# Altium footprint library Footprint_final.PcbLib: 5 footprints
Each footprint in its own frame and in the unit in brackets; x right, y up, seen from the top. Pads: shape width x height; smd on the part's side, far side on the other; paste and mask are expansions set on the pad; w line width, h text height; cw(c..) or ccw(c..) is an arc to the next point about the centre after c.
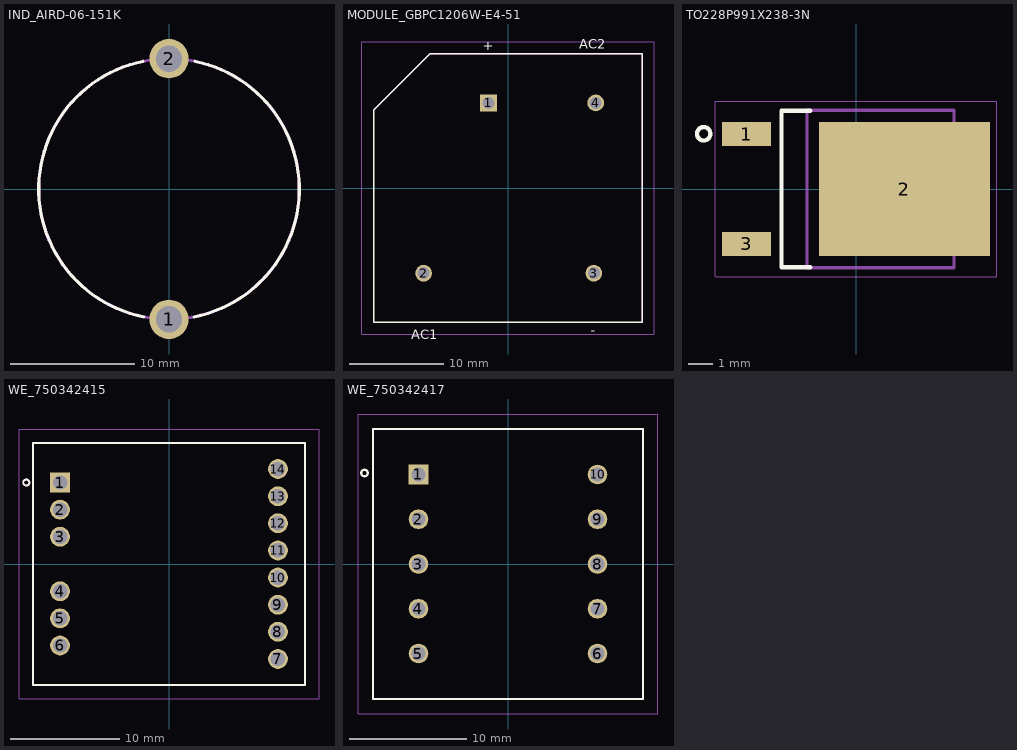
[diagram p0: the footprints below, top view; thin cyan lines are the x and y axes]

## IND_AIRD-06-151K [mm]
height 21
pads (2):
  round 3.175 hole 2.108: 1(0,-10.5) 2(0,10.5)
Top Overlay:
  lines w0.254: -2.086,10.291 ccw(c0,0) -2.035,-10.301 ; 2.035,-10.301 ccw(c0,0) 2.086,10.291
Mechanical 1:
  circle w0.254: c0,0 r10.5
Mechanical 5:
  text ".Designator" at -3.81,-0.381 h1.02
3D body: height 21.5, standoff 0.5, extent -10.417,-10.479 10.5,10.479

## MODULE_GBPC1206W-E4-51 [mm] "RECTIFIER 12A 600V GBPCW-4TH"
height 7.87
pads (4):
  rect 1.774x1.774 / inner round 1.774 / far side rect 1.774x1.774 hole 1.274: 1(-2.075,9.05)
  round 1.774 hole 1.274: 2(-8.975,-9.05) 3(9.125,-9.05) 4(9.325,9.05)
Top Overlay:
  lines w0.178: -14.275,-14.275 14.275,-14.275 14.275,14.275 -8.3,14.275 -14.275,8.3 -14.275,-14.275
  text ".Designator" at -1.524,16.5 h1.02
  text "AC2" at 7.57,14.828 h1.02
  text "AC1" at -10.273,-16.047 h1.02
  text "+" at -2.699,14.665 h1.02
  text "-" at 8.777,-15.583 h1.02
Bottom Overlay:
  lines w0.178: -14.275,-14.275 -14.275,-10 ; -14.275,-8.275 -14.275,-4 ; -14.275,-2.275 -14.275,2 ; -14.275,3.725 -14.275,8 ; -14,-14.275 -9.725,-14.275 ; -13.335,9.24 -9.271,13.304 ; -8,-14.275 -3.725,-14.275 ; -8,14.275 -4,14.275 ; -2.275,14.275 2,14.275 ; -2,-14.275 2.275,-14.275 ; 3.725,14.275 8,14.275 ; 4,-14.275 8.275,-14.275 ; 9.725,14.275 14,14.275 ; 10,-14.275 14.275,-14.275 ; 14.275,-14 14.275,-9.725 ; 14.275,-8 14.275,-3.725 ; 14.275,-2 14.275,2.275 ; 14.275,4 14.275,8.275 ; 14.275,10 14.275,14.275
Mechanical 5:
  lines w0.127: -14.275,-14.275 -14.275,8.3 -8.3,14.275 14.275,14.275 14.275,-14.275 -14.275,-14.275
  text ".Designator" at -1.524,-0.508 h1.02
  text "+" at -2.699,14.665 h1.02
  text "-" at 8.777,-15.583 h1.02
Mechanical 15:
  lines w0.05: -15.545,-15.545 15.545,-15.545 15.545,15.545 -15.545,15.545 -15.545,-15.545
Mechanical 17:
  text "LEAD LENGTH : 23.93MM" at -13.2,4.2 h1.27
3D body: height 7.87, standoff 0, extent -14.275,-14.275 14.275,14.275

## TO228P991X238-3N [mm] "IC, MOSFET N-CH, 500V, 200MA, DPAK"
height 2.38
pads (3):
  rect 2.05x1 smd: 1(-4.55,2.28) 3(-4.55,-2.28)
  rect 7.1x5.55 smd: 2(2,0)
Top Overlay:
  circle w0.178: c-6.326,2.291 r0.279
  lines w0.178: -1.9,-3.25 -3.1,-3.25 -3.1,3.25 -1.9,3.25
  text ".Designator" at -1.524,4 h1.02
Top Paste:
  region: 3.36,0.38 4.96,0.38 4.96,2.02 3.36,2.02
  region: 1.2,0.38 2.8,0.38 2.8,2.02 1.2,2.02
  region: -0.96,0.38 0.64,0.38 0.64,2.02 -0.96,2.02
  region: 3.36,-2.02 4.96,-2.02 4.96,-0.38 3.36,-0.38
  region: 1.2,-2.02 2.8,-2.02 2.8,-0.38 1.2,-0.38
  region: -0.96,-2.02 0.64,-2.02 0.64,-0.38 -0.96,-0.38
Mechanical 5:
  circle w0.127: c-6.326,2.291 r0.279
  lines w0.127: 4.065,-2.668 4.359,-2.668 4.955,-2.006 4.955,2.006 4.359,2.668 4.065,2.668 ; -2.03,-3.27 4.065,-3.27 4.065,3.27 -2.03,3.27 -2.03,-3.27
  text ".Designator" at -1.524,-0.508 h1.02
Mechanical 15:
  lines w0.05: -5.85,-3.65 -5.85,3.65 5.85,3.65 5.85,-3.65 -5.85,-3.65
Mechanical 20:
  circle w0.05: c0,0 r0.35
  lines w0.05: -0.5,0 0.5,0 ; 0,-0.5 0,0.5
3D body: height 2.38, standoff 0, extent -2.03,-3.27 4.065,3.27

## WE_750342415 [mm] "TRANSFOERMER, TH, 14-PIN"
height 16
pads (14):
  rect 1.82x1.82 / inner round 1.82 / far side rect 1.82x1.82 hole 1.32: 1(-10,7.48)
  round 1.82 hole 1.32: 2(-10,4.99) 3(-10,2.5) 4(-10,-2.5) 5(-10,-4.99) 6(-10,-7.48) 7(10,-8.715) 8(10,-6.225) 9(10,-3.735) 10(10,-1.245) 11(10,1.245) 12(10,3.735) 13(10,6.225) 14(10,8.715)
Top Overlay:
  circle w0.178: c-13.1,7.48 r0.279
  lines w0.178: -12.5,-11.1 12.5,-11.1 12.5,11.1 -12.5,11.1 -12.5,-11.1
  text ".Designator" at -1.524,12 h1.02
Bottom Overlay:
  lines w0.178: -12.5,-11.1 -12.5,-10.054 ; -12.5,-9.264 -12.5,-7.054 ; -12.5,-6.264 -12.5,-4.054 ; -12.5,-3.237 -12.5,-1.027 ; -12.5,-0.237 -12.5,1.973 ; -12.5,2.763 -12.5,4.973 ; -12.5,5.763 -12.5,7.973 ; -12.5,8.89 -12.5,11.1 -10.287,11.1 ; -10.894,-11.1 -8.627,-11.1 ; -9.5,11.1 -7.287,11.1 ; -7.894,-11.1 -5.627,-11.1 ; -6.5,11.1 -4.287,11.1 ; -4.894,-11.1 -2.627,-11.1 ; -3.5,11.1 -1.287,11.1 ; -1.894,-11.1 0.373,-11.1 ; -0.5,11.1 1.713,11.1 ; 1.106,-11.1 3.373,-11.1 ; 2.528,11.1 4.741,11.1 ; 4.106,-11.1 6.373,-11.1 ; 5.529,11.1 7.742,11.1 ; 7.106,-11.1 9.373,-11.1 ; 8.528,11.1 10.741,11.1 ; 10.233,-11.1 12.5,-11.1 12.5,-8.609 ; 12.5,-8.176 12.5,-5.685 ; 12.5,-5.176 12.5,-2.685 ; 12.5,-2.176 12.5,0.315 ; 12.5,0.824 12.5,3.315 ; 12.5,3.862 12.5,6.353 ; 12.5,6.862 12.5,9.353 ; 12.5,9.862 12.5,11.1
Mechanical 5:
  circle w0.127: c-13.1,7.48 r0.279
  lines w0.127: -12.5,-11.1 12.5,-11.1 12.5,11.1 -12.5,11.1 -12.5,-11.1
  text ".Designator" at -1.524,-0.508 h1.02
Mechanical 15:
  lines w0.05: -13.77,-12.37 -13.77,12.37 13.77,12.37 13.77,-12.37 -13.77,-12.37
Mechanical 17:
  text "LEAD LENGTH MAX: 4:00 MM" at -12.065,9.652 h1
3D body: height 16, standoff 0, extent -12.5,-11.1 12.5,11.1

## WE_750342417 [mm] "TRANSFOERMER, TH, 10-PIN"
height 17.53
pads (10):
  rect 1.67x1.67 / inner round 1.67 / far side rect 1.67x1.67 hole 1.17: 1(-7.62,7.62)
  round 1.67 hole 1.17: 2(-7.62,3.81) 3(-7.62,0) 4(-7.62,-3.81) 5(-7.62,-7.62) 6(7.62,-7.62) 7(7.62,-3.81) 8(7.62,0) 9(7.62,3.81) 10(7.62,7.62)
Top Layer:
  lines w0.178: 11.5,9 11.5,11.5
Top Overlay:
  circle w0.178: c-12.217,7.747 r0.279
  lines w0.178: -11.5,-11.5 11.5,-11.5 11.5,11.5 -11.5,11.5 -11.5,-11.5
  text ".Designator" at -1.524,12 h1.02
Bottom Overlay:
  lines w0.178: -11.5,-9.599 -11.5,-11.5 -9,-11.5 ; -11.5,-9.099 -11.5,-6.599 ; -11.5,-6.099 -11.5,-3.599 ; -11.5,-3.127 -11.5,-0.627 ; -11.5,-0.127 -11.5,2.373 ; -11.5,2.873 -11.5,5.373 ; -11.5,5.873 -11.5,8.373 ; -11.5,9 -11.5,11.5 -9,11.5 ; -8.5,-11.5 -6,-11.5 ; -8.5,11.5 -6,11.5 ; -5.5,-11.5 -3,-11.5 ; -5.5,11.5 -3,11.5 ; -2.5,-11.5 0,-11.5 ; -2.5,11.5 0,11.5 ; 0.5,-11.5 3,-11.5 ; 0.5,11.5 3,11.5 ; 3.5,-11.5 6,-11.5 ; 3.5,11.5 6,11.5 ; 6.5,-11.5 9,-11.5 ; 6.5,11.5 9,11.5 ; 9.5,-11.5 11.5,-11.5 11.5,-9.472 ; 9.5,11.5 11.5,11.5 11.5,9 ; 11.5,-8.972 11.5,-6.472 ; 11.5,-5.972 11.5,-3.472 ; 11.5,-3 11.5,-0.5 ; 11.5,0 11.5,2.5 ; 11.5,3 11.5,5.5 ; 11.5,6 11.5,8.5
Mechanical 5:
  circle w0.127: c-12.217,7.747 r0.279
  lines w0.127: -11.5,-11.5 11.5,-11.5 11.5,11.5 -11.5,11.5 -11.5,-11.5
  text ".Designator" at -1.524,-0.508 h1.02
Mechanical 15:
  lines w0.05: -12.77,-12.77 -12.77,12.77 12.77,12.77 12.77,-12.77 -12.77,-12.77
Mechanical 17:
  text "LEAD LENGTH MAX: 4:00 MM" at -11.684,9.652 h1
3D body: height 17.53, standoff 0, extent -11.5,-11.5 11.5,11.5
